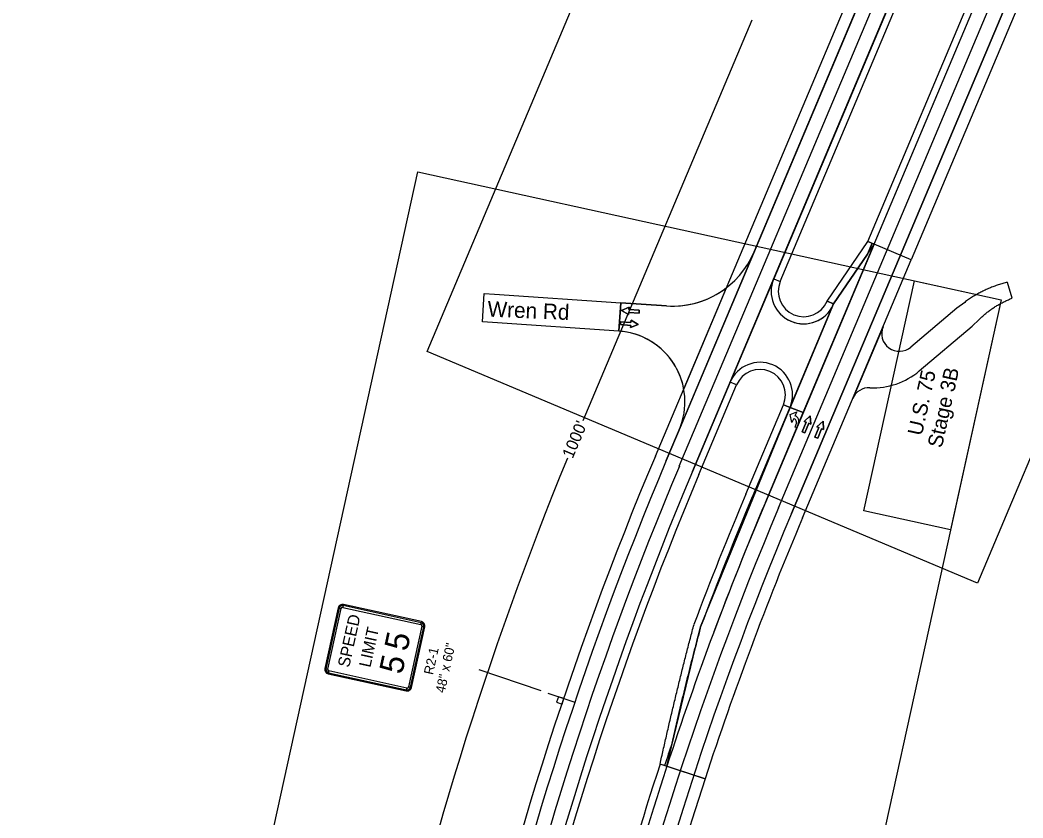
# Model space of a CAD drawing. Extents: x 14104283 to 14121738, y 8635219 to 8671666.
# Drawn here: x 14108596 to 14109444, y 8645129 to 8645804 of the extents above; entities that cross this region are included whole.
import ezdxf

# ---------------------------------------------------------------- set-up
doc = ezdxf.new("R2010")
doc.units = 0
for name, color, linetype in [('Cell', 7, 'Continuous'), ('Default', 7, 'Continuous'), ('dsnNonPlotable', 7, 'Continuous'), ('dsnPaintExistingBrokenLaneLineWhite', 7, 'Continuous'), ('dsnPaintExistingEdgeLineLeftYellow', 7, 'Continuous'), ('dsnPaintExistingEdgeLineRightWhite', 7, 'Continuous'), ('dsnPaintExistingLaneLineWhite', 7, 'Continuous'), ('dsnShadingGranular', 7, 'Continuous'), ('dsnShadingPaved', 7, 'Continuous'), ('dsnStdLabel', 7, 'Continuous'), ('dsnStgShadingPrevPav', 7, 'Continuous'), ('dsnTextFinalPlan', 7, 'Continuous'), ('dsnTextOverlapEven', 7, 'Continuous')]:
    doc.layers.add(name, color=color, linetype=linetype)

msp = doc.modelspace()

# ---------------------------------------------------------------- linework, layer by layer
at = {"layer": 'Cell'}
for p, q in [((14109250.67, 8645466.91), (14109250.38, 8645467.03)), ((14109251.49, 8645469.42), (14109251.66, 8645469.35)), ((14108869.07, 8645307.23), (14108869.4, 8645308.75)), ((14108935.53, 8645295.18), (14108869.6, 8645309.67)), ((14108865.14, 8645306.81), (14108853.87, 8645255.54)), ((14108866.05, 8645306.61), (14108867.58, 8645306.28)), ((14108935.33, 8645294.27), (14108934.99, 8645292.74)), ((14108927.12, 8645239.44), (14108938.39, 8645290.72)), ((14108935.95, 8645291.25), (14108937.47, 8645290.92)), ((14108856.31, 8645255), (14108854.79, 8645255.33)), ((14108856.73, 8645251.07), (14108922.66, 8645236.58)), ((14108856.93, 8645251.98), (14108857.26, 8645253.51)), ((14108923.19, 8645239.02), (14108922.86, 8645237.5)), ((14108926.21, 8645239.64), (14108924.68, 8645239.98)), ((14109042.45, 8645234.77), (14109065.2, 8645227.1))]:
    msp.add_line(p, q, dxfattribs=at)
for points in [[(14109119.8, 8645558.61), (14109119.6, 8645556.12), (14109110.88, 8645556.82), (14109110.73, 8645554.95), (14109104.75, 8645558.56), (14109111.23, 8645561.18), (14109111.08, 8645559.31)], [(14109103.82, 8645546.48), (14109104.02, 8645548.97), (14109112.74, 8645548.27), (14109112.89, 8645550.14), (14109118.87, 8645546.53), (14109112.39, 8645543.91), (14109112.54, 8645545.78)], [(14109259.91, 8645454.89), (14109257.59, 8645455.84), (14109260.91, 8645463.94), (14109259.18, 8645464.65), (14109264.44, 8645469.25), (14109264.96, 8645462.28), (14109263.23, 8645462.99)], [(14109270.68, 8645450.36), (14109268.36, 8645451.31), (14109271.69, 8645459.4), (14109269.95, 8645460.11), (14109275.21, 8645464.71), (14109275.73, 8645457.74), (14109274, 8645458.45)], [(14108935.33, 8645294.27), (14108869.4, 8645308.75), (14108869.07, 8645307.23), (14108934.99, 8645292.74), (14108935.33, 8645294.27)], [(14108866.05, 8645306.61), (14108854.79, 8645255.33), (14108856.31, 8645255), (14108867.58, 8645306.28), (14108866.05, 8645306.61)], [(14108926.21, 8645239.64), (14108937.47, 8645290.92), (14108935.95, 8645291.25), (14108924.68, 8645239.98), (14108926.21, 8645239.64)], [(14108856.93, 8645251.98), (14108922.86, 8645237.5), (14108923.19, 8645239.02), (14108857.26, 8645253.51), (14108856.93, 8645251.98)], [(14109056.03, 8645230.1), (14109051.38, 8645231.67), (14109049.81, 8645227.02), (14109054.46, 8645225.45)]]:
    msp.add_lwpolyline(points, close=True, dxfattribs=at)
for points in [[(14109111.08, 8645559.31), (14109111.23, 8645561.18), (14109104.75, 8645558.56), (14109110.73, 8645554.95), (14109110.88, 8645556.82), (14109119.6, 8645556.12), (14109119.8, 8645558.61), (14109111.08, 8645559.31)], [(14109112.54, 8645545.78), (14109112.39, 8645543.91), (14109118.87, 8645546.53), (14109112.89, 8645550.14), (14109112.74, 8645548.27), (14109104.02, 8645548.97), (14109103.82, 8645546.48), (14109112.54, 8645545.78)], [(14109247.3, 8645470.55), (14109253.04, 8645472.76), (14109251.49, 8645469.42)], [(14109247.3, 8645470.55), (14109253.04, 8645472.76), (14109251.49, 8645469.42)], [(14109250.38, 8645467.03), (14109248.83, 8645463.69), (14109247.3, 8645470.55)], [(14109250.38, 8645467.03), (14109248.83, 8645463.69), (14109247.3, 8645470.55)], [(14109250.67, 8645466.91), (14109250.38, 8645467.03)], [(14109251.49, 8645469.42), (14109251.66, 8645469.35)], [(14109254.3, 8645462.61), (14109252.92, 8645459.2), (14109251.54, 8645459.76), (14109252.52, 8645462.2)], [(14109254.3, 8645462.61), (14109252.92, 8645459.2), (14109251.54, 8645459.76), (14109252.52, 8645462.2)], [(14109263.23, 8645462.99), (14109264.96, 8645462.28), (14109264.44, 8645469.25), (14109259.18, 8645464.65), (14109260.91, 8645463.94), (14109257.59, 8645455.84), (14109259.91, 8645454.89), (14109263.23, 8645462.99)], [(14109274, 8645458.45), (14109275.73, 8645457.74), (14109275.21, 8645464.71), (14109269.95, 8645460.11), (14109271.69, 8645459.4), (14109268.36, 8645451.31), (14109270.68, 8645450.36), (14109274, 8645458.45)], [(14109056.03, 8645230.1), (14109051.38, 8645231.67), (14109049.81, 8645227.02), (14109054.46, 8645225.45), (14109056.03, 8645230.1)]]:
    msp.add_lwpolyline(points, dxfattribs=at)
for centre, radius, start, end in [((14108868.8, 8645306.01), 3.75, 77.60784, 167.60805), ((14108868.8, 8645306.01), 2.81, 77.60784, 167.60805), ((14108868.8, 8645306.01), 1.25, 77.60784, 167.60805), ((14108934.73, 8645291.52), 1.25, 347.60789, 77.6081), ((14108934.73, 8645291.52), 2.81, 347.60789, 77.6081), ((14108934.73, 8645291.52), 3.75, 347.60789, 77.6081), ((14108857.53, 8645254.73), 3.75, 167.60805, 257.60768), ((14108857.53, 8645254.73), 2.81, 167.60805, 257.60768), ((14108857.53, 8645254.73), 1.25, 167.60805, 257.60768), ((14108923.46, 8645240.25), 3.75, 257.60768, 347.60789), ((14108923.46, 8645240.25), 2.81, 257.60768, 347.60789), ((14108923.46, 8645240.25), 1.25, 257.60768, 347.60789)]:
    msp.add_arc(centre, radius, start, end, dxfattribs=at)
for centre, major_axis in [((14109249.29, 8645463.5), (-1.38, -3.41)), ((14109249.29, 8645463.5), (-1.38, -3.41)), ((14109249.68, 8645464.48), (-1.97, -4.87)), ((14109249.68, 8645464.48), (-1.97, -4.87))]:
    msp.add_ellipse(centre, major_axis=major_axis, ratio=0.9474, start_param=1.570796, end_param=3.141593, dxfattribs=at)
at = {"layer": 'Default'}
for points in [[(14118413.25, 8667444.25), (14110818.39, 8649409.15), (14109142.61, 8645431.44)], [(14109164.73, 8645422.12), (14110840.51, 8649399.84), (14118435.37, 8667434.94)]]:
    msp.add_lwpolyline(points, dxfattribs=at)
for radius in [2968, 2944]:
    msp.add_arc((14111877.8, 8644279.13), radius, 157.1547, 167.84877, dxfattribs=at)
at = {"layer": 'dsnNonPlotable'}
for points in [[(14108940.51, 8645523.76), (14109549.08, 8646968.3), (14110014.46, 8646772.24), (14109405.89, 8645327.7)], [(14108596.11, 8644144.86), (14108932.49, 8645675.84), (14109425.73, 8645567.47), (14109089.34, 8644036.49)]]:
    msp.add_lwpolyline(points, close=True, dxfattribs=at)
at = {"layer": 'dsnPaintExistingBrokenLaneLineWhite'}
for p, q in [((14109153.67, 8645426.78), (14110829.45, 8649404.5)), ((14109237.53, 8645391.45), (14110075.43, 8647380.31))]:
    msp.add_line(p, q, dxfattribs=at)
for centre, radius in [((14111877.8, 8644279.13), 2956), ((14111877.79, 8644279.13), 2865)]:
    msp.add_arc(centre, radius, 157.1547, 167.84877, dxfattribs=at)
at = {"layer": 'dsnPaintExistingEdgeLineLeftYellow'}
for p, q in [((14109318.52, 8645614.6), (14110902.26, 8649373.83)), ((14109283.61, 8645562.93), (14109318.29, 8645614.05)), ((14109196.6, 8645497.77), (14109164.73, 8645422.12)), ((14109171.7, 8645290.75), (14109247.29, 8645476.42)), ((14109143.12, 8645172.82), (14109171.7, 8645290.75))]:
    msp.add_line(p, q, dxfattribs=at)
msp.add_lwpolyline([(14111383.58, 8650689.44), (14110840.51, 8649399.84), (14109233.49, 8645585.32)], dxfattribs=at)
for centre, radius, start, end in [((14109258.83, 8645574.64), 27.5, 157.1547, 335.84151), ((14109221.94, 8645487.09), 27.5, 67.1547, 157.1547), ((14109221.94, 8645487.09), 27.5, 337.1547, 67.1547), ((14111877.8, 8644279.13), 2944, 157.1547, 167.84877), ((14111877.79, 8644279.13), 2877, 161.90302, 167.84877)]:
    msp.add_arc(centre, radius, start, end, dxfattribs=at)
at = {"layer": 'dsnPaintExistingEdgeLineRightWhite'}
for p, q in [((14109248.59, 8645386.79), (14110924.38, 8649364.51)), ((14109155.29, 8645461.54), (14109142.61, 8645431.44))]:
    msp.add_line(p, q, dxfattribs=at)
msp.add_lwpolyline([(14111344.56, 8650658.61), (14110818.39, 8649409.15), (14109217.02, 8645608.05)], dxfattribs=at)
for centre, radius in [((14111877.8, 8644279.13), 2968), ((14111877.79, 8644279.13), 2853)]:
    msp.add_arc(centre, radius, 157.1547, 167.84877, dxfattribs=at)
at = {"layer": 'dsnPaintExistingLaneLineWhite'}
msp.add_line((14109226.48, 8645396.11), (14109258.54, 8645472.23), dxfattribs=at)
msp.add_arc((14111877.79, 8644279.13), 2877, 157.1547, 159.50271, dxfattribs=at)
at = {"layer": 'dsnShadingGranular'}
msp.add_line((14109325.98, 8645544.73), (14109300.38, 8645483.96), dxfattribs=at)
at = {"layer": 'dsnShadingPaved'}
for p, q in [((14109258.54, 8645472.23), (14110902.26, 8649373.83)), ((14110924.38, 8649364.51), (14109248.59, 8645386.79)), ((14109318.29, 8645614.05), (14109258.54, 8645472.23)), ((14109283.61, 8645562.93), (14109318.29, 8645614.05)), ((14109153.74, 8645457.84), (14109217.02, 8645608.05)), ((14109196.6, 8645497.77), (14109233.49, 8645585.32)), ((14109104.08, 8645564.95), (14109102.47, 8645541)), ((14109142.87, 8645562.34), (14109104.08, 8645564.95)), ((14109171.7, 8645290.75), (14109247.29, 8645476.42)), ((14109247.29, 8645476.42), (14109258.54, 8645472.23)), ((14109258.54, 8645472.23), (14109247.29, 8645476.42)), ((14109143.12, 8645172.82), (14109171.7, 8645290.75))]:
    msp.add_line(p, q, dxfattribs=at)
for centre, radius, start, end in [((14109147.9, 8645637.17), 75, 266.1547, 337.1547), ((14109258.83, 8645574.64), 27.5, 157.1547, 247.1547), ((14109258.83, 8645574.64), 27.5, 247.1547, 335.84151), ((14109098.44, 8645481.13), 60, 337.1547, 86.1547), ((14109221.94, 8645487.09), 27.5, 67.1547, 157.1547), ((14109221.94, 8645487.09), 27.5, 337.1547, 67.1547), ((14111877.79, 8644279.13), 2853, 157.1547, 167.84877), ((14111877.79, 8644279.13), 2877, 161.90302, 167.84877)]:
    msp.add_arc(centre, radius, start, end, dxfattribs=at)
at = {"layer": 'dsnStdLabel'}
for p, q in [((14109214.96, 8645804.07), (14109072.17, 8645465.12)), ((14109036.86, 8645236.77), (14108984.36, 8645254.47))]:
    msp.add_line(p, q, dxfattribs=at)
msp.add_arc((14111877.8, 8644279.13), 3046, 157.72718, 167.84877, dxfattribs=at)
at = {"layer": 'dsnStgShadingPrevPav'}
for p, q in [((14109133.4, 8645435.32), (14110809.18, 8649413.03)), ((14110818.39, 8649409.15), (14109142.61, 8645431.44)), ((14109318.52, 8645614.6), (14109226.48, 8645396.11)), ((14109318.52, 8645614.6), (14109226.48, 8645396.11)), ((14109312.8, 8645606.16), (14109316.68, 8645615.38)), ((14109316.68, 8645615.38), (14109318.52, 8645614.6)), ((14109349.86, 8645601.4), (14109318.52, 8645614.6)), ((14109155.29, 8645461.54), (14109217.02, 8645608.05)), ((14109284.17, 8645563.96), (14109312.8, 8645606.16)), ((14109257.81, 8645382.91), (14109349.86, 8645601.4)), ((14109196.6, 8645497.77), (14109233.49, 8645585.32)), ((14109233.49, 8645585.32), (14109196.6, 8645497.77)), ((14109233.49, 8645585.32), (14109239.01, 8645582.99)), ((14109435.19, 8645568.84), (14109431.12, 8645582.24)), ((14109193.28, 8645577.45), (14109157.4, 8645492.29)), ((14109102.47, 8645541), (14109104.08, 8645564.95)), ((14109104.08, 8645564.95), (14109142.87, 8645562.34)), ((14109215.42, 8645400.77), (14109284.17, 8645563.96)), ((14109284.17, 8645563.96), (14109247.29, 8645476.42)), ((14109278.64, 8645566.29), (14109284.17, 8645563.96)), ((14109401.37, 8645545.2), (14109407.22, 8645550.87)), ((14109325.98, 8645544.73), (14109300.38, 8645483.96)), ((14109356.61, 8645507.27), (14109401.37, 8645545.2)), ((14109196.6, 8645497.77), (14109164.73, 8645422.12)), ((14109196.6, 8645497.77), (14109164.73, 8645422.12)), ((14109170.26, 8645419.79), (14109202.13, 8645495.44)), ((14109202.13, 8645495.44), (14109196.6, 8645497.77)), ((14109202.13, 8645495.44), (14109196.6, 8645497.77)), ((14109209.89, 8645403.09), (14109241.76, 8645478.75)), ((14109247.29, 8645476.42), (14109241.76, 8645478.75)), ((14109241.76, 8645478.75), (14109247.29, 8645476.42)), ((14109247.29, 8645476.42), (14109215.42, 8645400.77)), ((14109142.61, 8645431.44), (14109155.29, 8645461.54)), ((14109175.44, 8645162.26), (14109137.42, 8645174.69)), ((14109141.22, 8645173.44), (14109137.42, 8645174.69)), ((14109143.12, 8645172.82), (14109141.22, 8645173.44)), ((14109143.12, 8645172.82), (14109175.44, 8645162.26))]:
    msp.add_line(p, q, dxfattribs=at)
for points in [[(14109239.01, 8645582.99), (14111389.11, 8650687.11), (14111383.58, 8650689.44), (14109233.49, 8645585.32)], [(14109313, 8645616.93), (14110622.7, 8648725.72), (14110659.7, 8648710.5), (14109349.86, 8645601.4)], [(14109278.64, 8645566.29), (14109313, 8645616.93), (14109316.68, 8645615.38), (14109312.8, 8645606.16), (14109284.17, 8645563.96)], [(14108987.25, 8645548.72), (14108988.7, 8645572.67), (14108997.4, 8645572.12), (14109104.08, 8645564.95), (14109102.47, 8645541), (14108995.79, 8645548.17)]]:
    msp.add_lwpolyline(points, close=True, dxfattribs=at)
for points in [[(14111383.58, 8650689.44), (14110840.51, 8649399.84), (14109233.49, 8645585.32)], [(14109217.02, 8645608.05), (14110818.39, 8649409.15), (14111344.56, 8650658.61)], [(14109395, 8645565.3), (14109388.44, 8645560.45), (14109349.5, 8645527.46)]]:
    msp.add_lwpolyline(points, dxfattribs=at)
for centre, radius, start, end in [((14109258.83, 8645574.64), 21.5, 157.1547, 247.1547), ((14109147.9, 8645637.17), 75, 266.1547, 307.22827), ((14109258.83, 8645574.64), 21.5, 247.1547, 337.1547), ((14109098.44, 8645481.13), 60, 10.71201, 86.1547), ((14109339.81, 8645538.91), 15, 157.1547, 310.2778), ((14109221.94, 8645487.09), 21.5, 67.1547, 157.1547), ((14109221.94, 8645487.09), 21.5, 337.1547, 67.1547), ((14109317.82, 8645553.05), 60, 267.23357, 310.2778), ((14109314.2, 8645478.13), 15, 87.23357, 157.1547), ((14111877.8, 8644279.13), 2978, 157.1547, 167.84877), ((14111877.8, 8644279.13), 2968, 157.1547, 167.84877), ((14111877.8, 8644279.13), 2968, 157.1547, 167.84877), ((14111877.8, 8644279.13), 2944, 157.1547, 167.84877), ((14111877.8, 8644279.13), 2944, 157.1547, 167.84877), ((14111877.8, 8644279.13), 2938, 157.1547, 167.84877), ((14111877.79, 8644279.13), 2895, 157.1547, 159.50271), ((14111877.79, 8644279.13), 2877, 157.1547, 161.90253), ((14111877.79, 8644279.13), 2877, 157.1547, 161.90253), ((14111877.79, 8644279.13), 2889, 157.1547, 159.50271), ((14111877.79, 8644279.13), 2889, 157.1547, 159.50271), ((14111877.79, 8644279.13), 2843, 157.1547, 161.90253), ((14111877.79, 8644279.13), 2879, 161.50256, 161.90253), ((14111877.79, 8644279.13), 2879, 161.50256, 161.90253), ((14111877.79, 8644279.13), 2883, 161.90253, 167.84877), ((14111877.79, 8644279.13), 2843, 161.90253, 167.84877)]:
    msp.add_arc(centre, radius, start, end, dxfattribs=at)
for points in [[(14109431.12, 8645582.24), (14109430.48, 8645582.08), (14109429.19, 8645581.77), (14109427.27, 8645581.25), (14109425.36, 8645580.69), (14109423.46, 8645580.1), (14109421.57, 8645579.46), (14109419.69, 8645578.78), (14109417.82, 8645578.07), (14109415.97, 8645577.31), (14109414.12, 8645576.52), (14109412.3, 8645575.69), (14109410.49, 8645574.81), (14109408.69, 8645573.91), (14109406.91, 8645572.96), (14109405.15, 8645571.98), (14109403.4, 8645570.95), (14109401.68, 8645569.9), (14109399.98, 8645568.8), (14109398.29, 8645567.67), (14109396.63, 8645566.51), (14109395.54, 8645565.7), (14109395, 8645565.3)], [(14109407.22, 8645550.87), (14109407.62, 8645551.25), (14109408.41, 8645552.02), (14109409.62, 8645553.14), (14109410.86, 8645554.24), (14109412.12, 8645555.32), (14109413.4, 8645556.37), (14109414.71, 8645557.39), (14109416.05, 8645558.39), (14109417.4, 8645559.37), (14109418.77, 8645560.31), (14109420.17, 8645561.23), (14109421.59, 8645562.13), (14109423.03, 8645562.99), (14109424.48, 8645563.83), (14109425.96, 8645564.64), (14109427.45, 8645565.41), (14109428.97, 8645566.16), (14109430.5, 8645566.88), (14109432.04, 8645567.57), (14109433.61, 8645568.23), (14109434.66, 8645568.64), (14109435.19, 8645568.84)], [(14109137.42, 8645174.69), (14109137.85, 8645176.66), (14109138.73, 8645180.61), (14109140.05, 8645186.54), (14109141.39, 8645192.46), (14109142.74, 8645198.38), (14109144.1, 8645204.29), (14109145.48, 8645210.21), (14109146.86, 8645216.13), (14109148.27, 8645222.04), (14109149.68, 8645227.95), (14109151.11, 8645233.86), (14109152.55, 8645239.77), (14109154, 8645245.67), (14109155.46, 8645251.58), (14109156.94, 8645257.48), (14109158.43, 8645263.38), (14109159.94, 8645269.28), (14109161.45, 8645275.17), (14109162.98, 8645281.07), (14109164.52, 8645286.96), (14109165.56, 8645290.89), (14109166.08, 8645292.85)], [(14109147.53, 8645192.53), (14109147.9, 8645194.17), (14109148.65, 8645197.45), (14109149.78, 8645202.37), (14109150.93, 8645207.29), (14109152.08, 8645212.21), (14109153.24, 8645217.13), (14109154.41, 8645222.05), (14109155.58, 8645226.96), (14109156.77, 8645231.88), (14109157.97, 8645236.79), (14109159.17, 8645241.7), (14109160.38, 8645246.61), (14109161.6, 8645251.52), (14109162.83, 8645256.43), (14109164.07, 8645261.34), (14109165.32, 8645266.24), (14109166.58, 8645271.15), (14109167.85, 8645276.05), (14109169.12, 8645280.95), (14109170.4, 8645285.85), (14109171.27, 8645289.12), (14109171.7, 8645290.75)], [(14109171.7, 8645290.75), (14109171.27, 8645289.12), (14109170.4, 8645285.85), (14109169.12, 8645280.95), (14109167.85, 8645276.05), (14109166.58, 8645271.15), (14109165.32, 8645266.24), (14109164.07, 8645261.34), (14109162.83, 8645256.43), (14109161.6, 8645251.52), (14109160.38, 8645246.61), (14109159.17, 8645241.7), (14109157.97, 8645236.79), (14109156.77, 8645231.88), (14109155.58, 8645226.96), (14109154.41, 8645222.05), (14109153.24, 8645217.13), (14109152.08, 8645212.21), (14109150.93, 8645207.29), (14109149.78, 8645202.37), (14109148.65, 8645197.45), (14109147.9, 8645194.17), (14109147.53, 8645192.53)]]:
    msp.add_open_spline(points, degree=3, dxfattribs=at)
at = {"layer": 'dsnTextOverlapEven'}
for points in [[(14109425.73, 8645567.47), (14109382.96, 8645372.83), (14109309.71, 8645388.93), (14109352.48, 8645583.57)], [(14109309.71, 8645388.93), (14109352.48, 8645583.57), (14109425.73, 8645567.47), (14109382.96, 8645372.83)]]:
    msp.add_lwpolyline(points, close=True, dxfattribs=at)

# ---------------------------------------------------------------- texts
at = {"layer": 'Cell'}
for s, height, p in [('SPEED', 10, (14108874.41, 8645255.8)), ('LIMIT', 10, (14108892.34, 8645255.89)), ('5', 20, (14108923.46, 8645269.38)), ('48" x 60"', 8, (14108955.18, 8645234.33)), ('5', 20, (14108919.17, 8645249.85)), ('R2-1', 8, (14108945.26, 8645249.77))]:
    msp.add_text(s, height=height, rotation=77.60784, dxfattribs=at).set_placement(p)
at = {"layer": 'dsnStdLabel'}
msp.add_text("1000'", height=10, rotation=67.05307, dxfattribs=at).set_placement((14109063.42, 8645432.55))
at = {"layer": 'dsnTextFinalPlan'}
msp.add_text('Wren Rd', height=13.125, rotation=357.6374, dxfattribs=at).set_placement((14108991.27, 8645553.28))
at = {"layer": 'dsnTextOverlapEven'}
for s, p in [('U.S. 75', (14109358.74, 8645451.91)), ('Stage 3B', (14109375.66, 8645441.54))]:
    msp.add_text(s, height=12.5, rotation=77.60784, dxfattribs=at).set_placement(p)

doc.saveas('drawing.dxf')
